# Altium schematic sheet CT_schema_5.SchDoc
size 218 x 258 mm
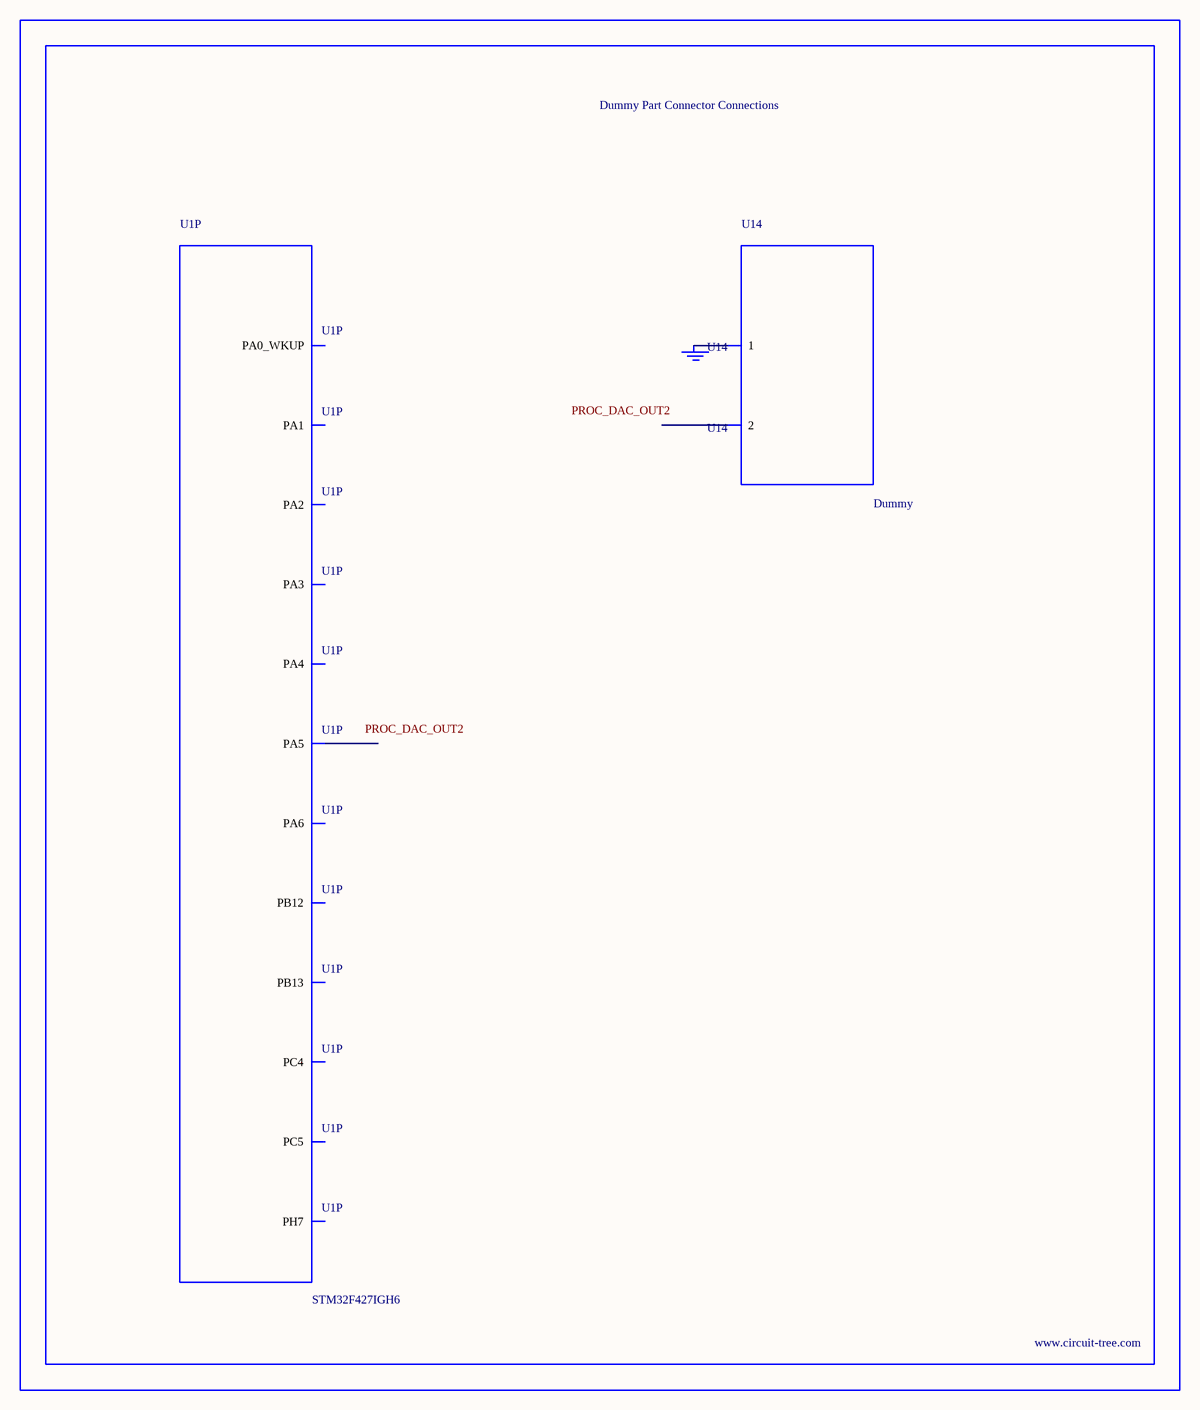
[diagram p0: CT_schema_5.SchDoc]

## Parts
BORDER4  (no value)
GND_INSTANCE_4_0  (no value)
U1  STM32F427IGH6  [UFBGA176_25]  (part P of 16)
U14  Dummy  [DUMMY_PACKAGE_168]

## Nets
NetGND_INSTANCE_4_0_0: GND_INSTANCE_4_0.0(GND) U14.1

Not connected (* = marked no-connect by the designer): U1 N2(PA1) N3(PA0_WKUP) N4(PA4) N5(PC4) N12(PH7) P2(PA2) P3(PA6) P4(PA5) P5(PC5) P12(PB12) P13(PB13) R2(PA3); U14 2

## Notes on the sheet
- Labels drawn without touching a wire or pin: PROC_DAC_OUT2

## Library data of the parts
BORDER4 = BORDER_PAGE4
GND_INSTANCE_4_0 = GND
